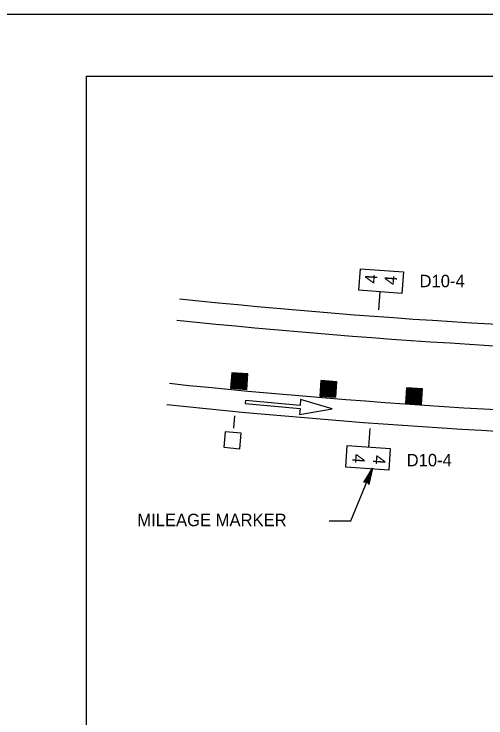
# Model space of a CAD drawing. Extents: x 640253 to 641999, y 298458 to 299646.
# Drawn here: x 641116.9 to 641231, y 299475.5 to 299645.6 of the extents above; entities that cross this region are included whole.
import ezdxf

# ---------------------------------------------------------------- set-up
doc = ezdxf.new("R2010")
doc.units = 0
for name, color, linetype in [('1', 7, 'Continuous'), ('2', 7, 'Continuous'), ('PLT-BNDY', 7, 'Continuous')]:
    doc.layers.add(name, color=color, linetype=linetype)

msp = doc.modelspace()

# ---------------------------------------------------------------- linework, layer by layer
at = {"layer": '1'}
for q in [(641920.31, 299630.63), (641134.31, 299066.63)]:
    msp.add_line((641134.31, 299630.63), q, dxfattribs=at)
at = {"layer": '2'}
for p, q in [((641205.09, 299574.16), (641205.4, 299578.5)), ((641172.82, 299552.2), (641172.75, 299551.49)), ((641186.01, 299550.99), (641172.82, 299552.2)), ((641186.14, 299552.43), (641186.01, 299550.99)), ((641193.78, 299550.25), (641186.14, 299552.43)), ((641172.75, 299551.49), (641186.02, 299550.28)), ((641186.02, 299550.28), (641185.89, 299548.84)), ((641185.89, 299548.84), (641193.78, 299550.25)), ((641169.98, 299545.5), (641170.21, 299548.48)), ((641202.9, 299545.44), (641202.58, 299540.96))]:
    msp.add_line(p, q, dxfattribs=at)
for points in [[(641200.23, 299578.87), (641200.61, 299584.06), (641211, 299583.31), (641210.63, 299578.12)], [(641167.6, 299540.91), (641171.48, 299540.57), (641171.81, 299544.31), (641167.93, 299544.65)], [(641207.84, 299540.59), (641207.46, 299535.4), (641197.07, 299536.15), (641197.44, 299541.34)]]:
    msp.add_lwpolyline(points, close=True, dxfattribs=at)
for points in [[(641169.23, 299555.17), (641173.12, 299554.9), (641173.38, 299558.64), (641169.49, 299558.91), (641169.23, 299555.17), (641173.31, 299558.57), (641169.55, 299558.84), (641169.3, 299555.22), (641173.06, 299554.96), (641173.31, 299558.51), (641169.62, 299558.76), (641169.38, 299555.28), (641172.98, 299555.03), (641173.21, 299558.42), (641169.68, 299558.67), (641169.45, 299555.34), (641172.92, 299555.09), (641173.15, 299558.37), (641169.75, 299558.61), (641169.52, 299555.39), (641172.85, 299555.16), (641173.06, 299558.31), (641169.81, 299558.54), (641169.58, 299555.45), (641172.79, 299555.24), (641172.98, 299558.24), (641169.88, 299558.46), (641169.66, 299555.51), (641172.72, 299555.31), (641172.91, 299558.17), (641169.94, 299558.38), (641169.72, 299555.58), (641172.64, 299555.4), (641172.83, 299558.09), (641170.02, 299558.3), (641169.8, 299555.62), (641172.55, 299555.48), (641172.74, 299558.04), (641170.09, 299558.22), (641169.88, 299555.69), (641172.48, 299555.55), (641172.65, 299557.99), (641170.17, 299558.14), (641169.96, 299555.72), (641172.39, 299555.62), (641172.54, 299557.92), (641170.25, 299558.04), (641170.12, 299556.95), (641170.04, 299555.79), (641172.32, 299555.7), (641172.44, 299557.82), (641170.32, 299557.93), (641170.13, 299555.85), (641172.24, 299555.78), (641172.34, 299557.75), (641170.42, 299557.83), (641170.24, 299555.93), (641172.11, 299555.85), (641172.22, 299557.63), (641170.55, 299557.71), (641170.37, 299556.05), (641171.98, 299555.97), (641172.07, 299557.54), (641170.69, 299557.58), (641170.52, 299556.16), (641170.52, 299556.16), (641171.84, 299556.12), (641171.92, 299557.4), (641170.82, 299557.44), (641170.67, 299556.28), (641171.7, 299556.27), (641171.77, 299557.26), (641170.95, 299557.3), (641170.85, 299556.42), (641171.55, 299556.4), (641171.57, 299557.14), (641171.1, 299557.15), (641171.04, 299556.55), (641171.38, 299556.55), (641171.41, 299557), (641171.27, 299557.04), (641171.22, 299556.68)], [(641190.77, 299553.3), (641194.66, 299553.02), (641194.92, 299556.76), (641191.03, 299557.03), (641190.77, 299553.3), (641194.85, 299556.7), (641191.09, 299556.96), (641190.84, 299553.34), (641194.6, 299553.08), (641194.84, 299556.63), (641191.16, 299556.89), (641190.92, 299553.4), (641194.52, 299553.15), (641194.75, 299556.55), (641191.22, 299556.79), (641190.99, 299553.46), (641194.46, 299553.22), (641194.69, 299556.49), (641191.29, 299556.73), (641191.06, 299553.51), (641194.39, 299553.29), (641194.6, 299556.43), (641191.35, 299556.66), (641191.12, 299553.57), (641194.33, 299553.36), (641194.51, 299556.36), (641191.41, 299556.58), (641191.2, 299553.63), (641194.26, 299553.43), (641194.44, 299556.3), (641191.48, 299556.51), (641191.26, 299553.7), (641194.18, 299553.52), (641194.37, 299556.21), (641191.56, 299556.42), (641191.33, 299553.75), (641194.09, 299553.6), (641194.27, 299556.16), (641191.63, 299556.34), (641191.42, 299553.81), (641194.01, 299553.67), (641194.18, 299556.11), (641191.7, 299556.26), (641191.5, 299553.84), (641193.93, 299553.74), (641194.08, 299556.04), (641191.79, 299556.17), (641191.66, 299555.07), (641191.58, 299553.91), (641193.86, 299553.82), (641193.98, 299555.95), (641191.86, 299556.06), (641191.67, 299553.98), (641193.77, 299553.9), (641193.88, 299555.88), (641191.96, 299555.95), (641191.78, 299554.06), (641193.65, 299553.97), (641193.76, 299555.76), (641192.08, 299555.84), (641191.91, 299554.17), (641193.52, 299554.09), (641193.61, 299555.66), (641192.23, 299555.7), (641192.06, 299554.28), (641192.06, 299554.28), (641193.38, 299554.24), (641193.46, 299555.52), (641192.36, 299555.56), (641192.21, 299554.4), (641193.23, 299554.39), (641193.31, 299555.38), (641192.49, 299555.42), (641192.38, 299554.54), (641193.09, 299554.52), (641193.11, 299555.26), (641192.64, 299555.27), (641192.58, 299554.67), (641192.92, 299554.67), (641192.95, 299555.12), (641192.81, 299555.16), (641192.76, 299554.8)], [(641211.51, 299551.56), (641215.4, 299551.29), (641215.66, 299555.02), (641211.77, 299555.29), (641211.51, 299551.56), (641215.59, 299554.95), (641211.84, 299555.22), (641211.58, 299551.6), (641215.34, 299551.34), (641215.59, 299554.89), (641211.91, 299555.15), (641211.66, 299551.66), (641215.27, 299551.41), (641215.5, 299554.81), (641211.97, 299555.05), (641211.73, 299551.72), (641215.21, 299551.48), (641215.43, 299554.75), (641212.03, 299554.99), (641211.81, 299551.77), (641215.13, 299551.55), (641215.34, 299554.69), (641212.1, 299554.92), (641211.87, 299551.83), (641215.07, 299551.62), (641215.26, 299554.62), (641212.16, 299554.84), (641211.94, 299551.89), (641215.01, 299551.69), (641215.19, 299554.56), (641212.22, 299554.77), (641212.01, 299551.96), (641214.92, 299551.78), (641215.11, 299554.47), (641212.31, 299554.68), (641212.08, 299552.01), (641214.83, 299551.86), (641215.02, 299554.42), (641212.38, 299554.61), (641212.16, 299552.07), (641214.76, 299551.93), (641214.93, 299554.37), (641212.45, 299554.52), (641212.24, 299552.11), (641214.68, 299552), (641214.83, 299554.3), (641212.53, 299554.43), (641212.41, 299553.33), (641212.32, 299552.17), (641214.6, 299552.09), (641214.73, 299554.21), (641212.6, 299554.32), (641212.42, 299552.24), (641214.52, 299552.16), (641214.63, 299554.14), (641212.7, 299554.21), (641212.53, 299552.32), (641214.4, 299552.23), (641214.51, 299554.02), (641212.83, 299554.1), (641212.66, 299552.44), (641214.26, 299552.35), (641214.35, 299553.92), (641212.98, 299553.96), (641212.8, 299552.54), (641212.81, 299552.54), (641214.13, 299552.5), (641214.21, 299553.79), (641213.11, 299553.82), (641212.95, 299552.66), (641213.98, 299552.65), (641214.06, 299553.64), (641213.23, 299553.68), (641213.13, 299552.8), (641213.83, 299552.78), (641213.86, 299553.52), (641213.39, 299553.53), (641213.32, 299552.93), (641213.67, 299552.93), (641213.7, 299553.38), (641213.55, 299553.42), (641213.51, 299553.06)], [(641193.09, 299523.13), (641198.3, 299523.13), (641203.52, 299535.88)], [(641201.65, 299532.57), (641201.96, 299532.59), (641203.52, 299535.88), (641201.65, 299532.57), (641201.42, 299532.44), (641203.52, 299535.88), (641202.32, 299532.44), (641202.5, 299532.21), (641203.52, 299535.88), (641202.61, 299531.96), (641202.5, 299532.21)]]:
    msp.add_lwpolyline(points, dxfattribs=at)
for radius, start, end in [(1613.21, 264.03084, 274.7698), (1618.4, 264.02808, 274.75447), (1633.8, 264.01999, 274.70955), (1638.99, 264.0173, 274.6946)]:
    msp.add_arc((641324.62, 301181.29), radius, start, end, dxfattribs=at)
at = {"layer": 'PLT-BNDY'}
msp.add_lwpolyline([(641094.31, 299645.63), (641935.31, 299645.63), (641935.31, 299051.63), (641094.31, 299051.63)], close=True, dxfattribs=at)

# ---------------------------------------------------------------- texts
at = {"layer": '2'}
for rotation, p in [(85.8569, (641204.62, 299580.41)), (85.8569, (641209.33, 299580.07)), (265.8569, (641198.77, 299539.41)), (265.8569, (641203.77, 299539.09))]:
    msp.add_text('4', height=3, rotation=rotation, dxfattribs=at).set_placement(p)
for s, p in [('D10-4', (641214.91, 299579.61)), ('D10-4', (641211.79, 299536.32)), ('MILEAGE MARKER', (641146.66, 299521.85))]:
    msp.add_text(s, height=3, dxfattribs=at).set_placement(p)

doc.saveas('drawing.dxf')
